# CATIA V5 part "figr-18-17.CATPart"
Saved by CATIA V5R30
Part number: Part1
Bounding box of the stored display mesh (mm): x -145.664 to 56.336, y -59.016 to 59.016, z 0 to 59.016
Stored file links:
  D:\PROJECTS\CATIA V56R 2020\Resources\Parts File\c18_catia_v6_6r2020_prt\figr-18-17.CATPart
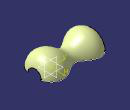
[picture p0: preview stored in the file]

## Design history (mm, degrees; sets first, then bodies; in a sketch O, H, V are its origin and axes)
Body1 (main body)
  Sketch1 on xy-plane, origin (0, 0, 0), H (0, 1, 0), V (-1, 0, 0)
    axis line L1 (0, 123.8615) -> (0, -59.1385)
    point P1 (0, 123.8615)
    point P3 (0, -34.0335)
    spline S1 through (23.6546, -56.3365) (51.0796, -40.3365) (54.2281, 7) (30.2281, 53.4991) (54.2281, 100.4991) (46.6546, 145.6635)
    coincidence: P1 V, P3 L1
    vertical: L1 V
  Revol1: Element1 Sketch1, Angle1 180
